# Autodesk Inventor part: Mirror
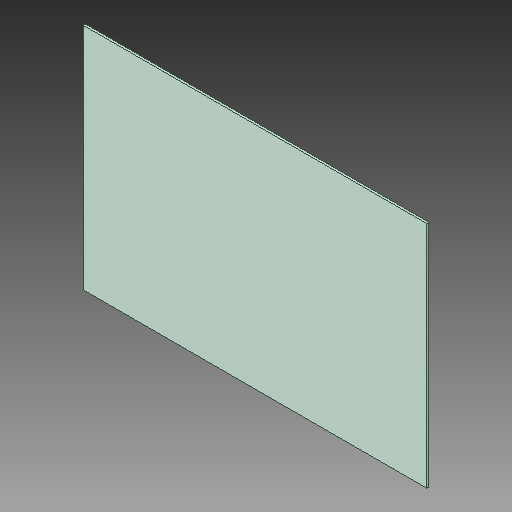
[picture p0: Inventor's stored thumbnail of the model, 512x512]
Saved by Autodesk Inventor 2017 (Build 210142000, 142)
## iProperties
Created: 2017-05
Part Number: Mirror
Material: Generic
Document SubType Name: Modeling
Designer: Savy
Density: 1 g/cm^3
Appearance: Default
Author: Savy
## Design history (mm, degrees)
feature "SOLID1"
body "Solid1"
